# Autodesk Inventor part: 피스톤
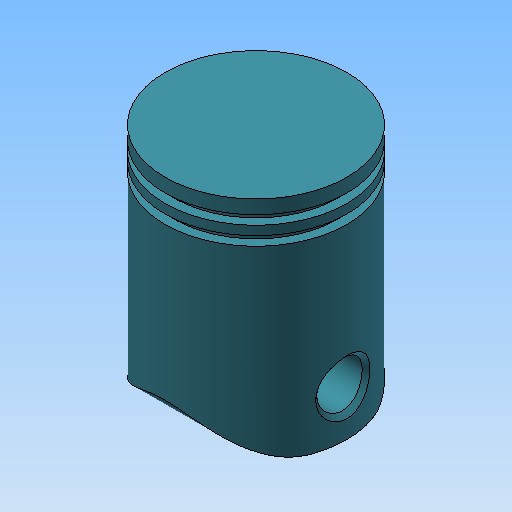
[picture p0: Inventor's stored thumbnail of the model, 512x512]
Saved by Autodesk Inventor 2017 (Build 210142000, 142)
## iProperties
Created: 2017-05
Part Number: 피스톤
Material: 알루미늄 6061
Document SubType Name: Modeling
Designer: mduedu
Density: 2.71 g/cm^3
Mass: 87.6982 g
Surface Area: 150.47 cm^2
Volume: 32.361 cm^3
Appearance: 커뎃 파란색
Author: mduedu
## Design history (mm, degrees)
sketch "스케치1"
  geometry: L1 (0, 0)-(20, 0); L2 (20, -50)-(15, -50); L3 (15, -50)-(15, -5); L4 (15, -5)-(0, -5); L5 (0, -5)-(0, 0); L6 (20, -3)-(18, -3); L7 (18, -3)-(18, -5); L8 (18, -5)-(20, -5); L9 (20, -7)-(18, -7); L10 (18, -7)-(18, -9); L11 (18, -9)-(20, -9); L12 (20, 0)-(20, -3); L13 (20, -5)-(20, -7); L14 (20, -9)-(20, -50); L15 (0, -60)-(0, 10) reference
  constraints: 28 end point, 10 parallel, 5 perpendicular, 4 collinear, 3 horizontal
  dimensions: "d0" = 20 distance of L1.start L1.end; "d1" = 2 distance of L6.start L6.end; "d2" = 2 distance of L6.end L7.end; "d3" = 2 distance of L8.end L9.start; "d4" = 3 distance of L1.end L6.start; "d5" = 5 distance of L2.start L2.end; "d6" = 50 distance between parallel lines of L1 L2; "d7" = 5 distance of L4.end L1.start
revolve "회전1" sketch "스케치1" stored, may be unused: angle "d8" = 90 deg
fillet "모깎기1" dims "d9" = 1
sketch "스케치2"
  geometry: L1 (-50, 15)-(-50, -15) reference; C1 r 10 at (-40, 0); 1 further point
  constraints: 1 centre point, 1 horizontal alignment
  dimensions: "d10" = 20 diameter of C1; "d11" = 10 distance from line of C1.centre L1
extrude "돌출1" join sketch "스케치2" stored distance "d12" = 10; taper "d13" = 0 deg
sketch "스케치3"
  geometry: L1 (0, -20)-(-3, -20) reference; L2 (-3, -20)-(-3, -18) reference; L3 (-3, -18)-(-5, -18) reference; L4 (-5, -18)-(-5, -20) reference; L5 (-5, -20)-(-7, -20) reference; L6 (-7, -20)-(-7, -18) reference; L7 (-7, -18)-(-9, -18) reference; L8 (-9, -18)-(-9, -20) reference; L9 (-9, -20)-(-50, -20) reference; L10 (-50, -20)-(-50, -15) reference; L11 (-50, -15)-(-6, -15) reference; L12 (-5, -14)-(-5, 14) reference; L13 (-6, 15)-(-50, 15) reference; L14 (-50, 15)-(-50, 20) reference; L15 (-50, 20)-(-9, 20) reference; L16 (-9, 20)-(-9, 18) reference; L17 (-9, 18)-(-7, 18) reference; L18 (-7, 18)-(-7, 20) reference; L19 (-7, 20)-(-5, 20) reference; L20 (-5, 20)-(-5, 18) reference; L21 (-5, 18)-(-3, 18) reference; L22 (-3, 18)-(-3, 20) reference; L23 (-3, 20)-(0, 20) reference; L24 (0, 20)-(0, -20) reference; C1 r 10 at (-40, 0) reference; C2 r 5 at (-40, 0); A1 r 1 centre (-6, -14) between (-6, -15) and (-5, -14) reference; A2 r 1 centre (-6, 14) between (-5, 14) and (-6, 15) reference; 1 further point
  constraints: 1 centre point, 1 coincident
  dimensions: "d15" = 10 diameter of C2
extrude "돌출2" cut sketch "스케치3" stored distance "d16" = 10; taper "d17" = 0 deg
sketch "스케치4"
  geometry: L1 (15, -50)-(-15, -50) reference; L2 (-15, -50)-(-20, -50) reference; L3 (-20, -50)-(-20, -45) reference; L4 (20, -45)-(20, -50) reference; L5 (20, -50)-(15, -50) reference; L6 (-15, -30)-(15, -30) reference; L7 (15, -30)-(15, -6) reference; L8 (14, -5)-(-14, -5) reference; L9 (-15, -6)-(-15, -30) reference; L10 (-20, -3)-(-20, 0) reference; L11 (-20, 0)-(20, 0) reference; L12 (20, 0)-(20, -3) reference; L13 (20, -3)-(18, -3) reference; L14 (18, -3)-(18, -5) reference; L15 (18, -5)-(20, -5) reference; L16 (20, -5)-(20, -7) reference; L17 (20, -7)-(18, -7) reference; L18 (18, -7)-(18, -9) reference; L19 (18, -9)-(20, -9) reference; L20 (-20, -9)-(-18, -9) reference; L21 (-18, -9)-(-18, -7) reference; L22 (-18, -7)-(-20, -7) reference; L23 (-20, -7)-(-20, -5) reference; L24 (-20, -5)-(-18, -5) reference; L25 (-18, -5)-(-18, -3) reference; L26 (-18, -3)-(-20, -3) reference; L27 (0, 0)-(0, -50); L28 (-5.698, -50)-(-5, -30); L29 (5.698, -50)-(5, -30); L30 (-5, -30)-(5, -30); L31 (-5.698, -50)-(5.698, -50); L32 (-20, -45)-(20, -45) reference; L33 (20, -9)-(20, -35) reference; L34 (20, -35)-(-20, -35) reference; L35 (-20, -35)-(-20, -9) reference; A1 r 1 centre (14, -6) between (15, -6) and (14, -5) reference; A2 r 1 centre (-14, -6) between (-14, -5) and (-15, -6) reference
  constraints: 10 end point, 2 point on line, 2 symmetric about line, 1 midpoint, 1 parallel, 1 perpendicular
  dimensions: "d18" = 2 deg angle of L27 L28; "d19" = 5 distance from line of L27 L28.end
extrude "돌출3" cut sketch "스케치4" stored distance "d20" = 20; taper "d21" = 0 deg
chamfer "모따기1" distance "d22" = 1; stored, may be unused: second distance "d23" = 2, angle "d24" = 45 deg
sketch "스케치5"
  geometry: L1 (-50, 0)-(-50, -15) reference; L2 (-50, 15)-(-50, 0) reference; L3 (-9, 20)-(-50, 20) reference; L4 (-50, 20)-(-50, -20) reference; L5 (-9, -20)-(-50, -20) reference; L6 (-42.483, -20)-(-50, -20); L7 (-50, -20)-(-50, -7); L8 (-42.483, 20)-(-50, 20); L9 (-50, 20)-(-50, 7); A1 r 15 centre (-35, 7) between (-42.483, 20) and (-50, 7); A2 r 15 centre (-35, -7) between (-42.483, -20) and (-50, -7); 1 further point
  constraints: 8 end point, 4 point on circle, 4 point on line, 2 centre point, 2 tangent, 1 collinear, 1 equal radius, 1 perpendicular
  dimensions: "d25" = 30 diameter of A1; "d26" = 7 vertical distance of A2.centre point (0, 0); "d27" = 7 vertical distance of point (0, 0) A1.centre (= d26)
extrude "돌출4" cut sketch "스케치5" stored distance "d28" = 20; taper "d29" = 0 deg
node "솔리드1"
node "절단 모서리 투영1"
node "절단 모서리 투영2"
